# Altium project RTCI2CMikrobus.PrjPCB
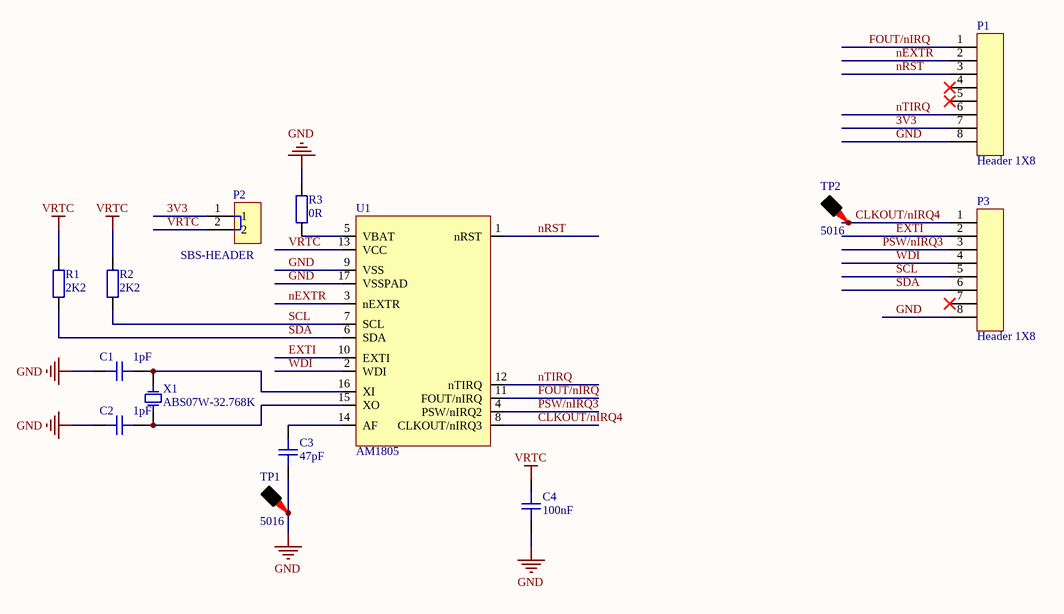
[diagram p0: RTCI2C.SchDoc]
1 sheet, 14 parts. Net scope: global (net labels, ports and power ports of the same name join across sheets).
Board file: RTCI2C.PcbDoc

## Sheet RTCI2C.SchDoc
size A4; Organization: Altium Limited; Address1: L3, 12a Rodborough Rd; Address2: Frenchs Forest; Address3: NSW; Address4: Australia 2086

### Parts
C1  1pF  [CAPC1005N]
C2  1pF  [CAPC1005N]
C3  47pF  [CAPC1005N]
C4  100nF  [CAPC1005N]
P1  Header 1X8  [HEADER1X8]
P2  SBS-HEADER  [SBS-HEADER]  (net tie, no BOM)
P3  Header 1X8  [HEADER1X8]
R1  2K2  [RESC1005N]
R2  2K2  [RESC1005N]
R3  0R  [RESC1005N]
TP1  5016  [5016]
TP2  5016  [5016]
U1  AM1805  [QFN50P300X300-16W4L]
X1  ABS07W-32.768K  [ABS07W]

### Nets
GND: C1.2 C2.2 C3.1 C4.1 P1.8 P3.8 R3.2 TP1.1 U1.9(VSS) U1.17(VSSPAD)
VRTC: C4.2 P2.2 R1.2 R2.2 U1.13(VCC)
3V3: P1.7 P2.1
CLKOUT/nIRQ4: P3.1 TP2.1 U1.8(CLKOUT/nIRQ3)
EXTI: P3.2 U1.10(EXTI)
FOUT/nIRQ: P1.1 U1.11(FOUT/nIRQ)
nEXTR: P1.2 U1.3(nEXTR)
nRST: P1.3 U1.1(nRST)
nTIRQ: P1.6 U1.12(nTIRQ)
PSW/nIRQ3: P3.3 U1.4(PSW/nIRQ2)
SCL: P3.5 R2.1 U1.7(SCL)
SDA: P3.6 R1.1 U1.6(SDA)
WDI: P3.4 U1.2(WDI)
NetC1_1: C1.1 U1.16(XI) X1.2
NetC2_1: C2.1 U1.15(XO) X1.1
NetC3_2: C3.2 U1.14(AF)
NetR3_1: R3.1 U1.5(VBAT)

Not connected (* = marked no-connect by the designer): P1 4* 5*; P3 7*

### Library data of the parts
C1-C4 = CAP_CHP: Surface Mount Unpolarized Capacitor
P1 P3 = HDR1X8
R1-R3 = RES_CHP: Surface Mount Resistor
TP1 TP2 = TP: Test Point
U1 = AM1805: AM18X5 Real-Time Clock with Power / Management Family
X1 = ABS07W: 32.768KHZ IoT OPTIMIZED SMD CRYSTAL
